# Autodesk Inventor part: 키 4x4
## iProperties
Created: 2014-10
Part Number: 키 4x4
Document SubType Name: Modeling
Designer: KYOUNG IL JANG
Density: 1 g/cm^3
Mass: 0.210265 g
Surface Area: 2.35398 cm^2
Volume: 0.210265 cm^3
Author: SeoGD™ [www.esajin.kr]
Revision Number: 1
